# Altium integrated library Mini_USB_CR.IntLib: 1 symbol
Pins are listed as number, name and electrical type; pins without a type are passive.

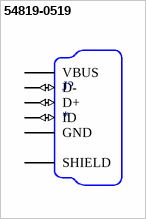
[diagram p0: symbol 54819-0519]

## 54819-0519
designator J?
USB - mini B USB 2.0 OTG Receptacle Connector 5 Position Through Hole, Right Angle; MP: 54819-0519; MF: Molex
footprint MOLEX_54819-0519
pins: 1 VBUS (power), 2 D- (io), 3 D+ (io), 4 ID (io), 5 GND (power), 6 VBUS (power), 7 D- (io), 8 D+ (io), 9 ID (io), 10 GND (power), 11 SHIELD, 12 SHIELD, S1 SHIELD, S2 SHIELD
